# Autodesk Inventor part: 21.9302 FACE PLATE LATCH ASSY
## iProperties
Created: 2011-01
Part Number: 21.9302 FACE PLATE LATCH ASSY
Document SubType Name: Modeling
Designer: Administrator
Density: 7.85 g/cm^3
Material: Steel
Mass: 212.96 g
Surface Area: 101.534 cm^2
Volume: 27.1287 cm^3
Author: Administrator
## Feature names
1. Extrusion1
2. Hole1
3. Extrusion2
4. Extrusion3
5. Extrusion4
6. Extrusion5
7. Extrusion6
8. Fillet1
9. Extrusion7
10. Fillet2
